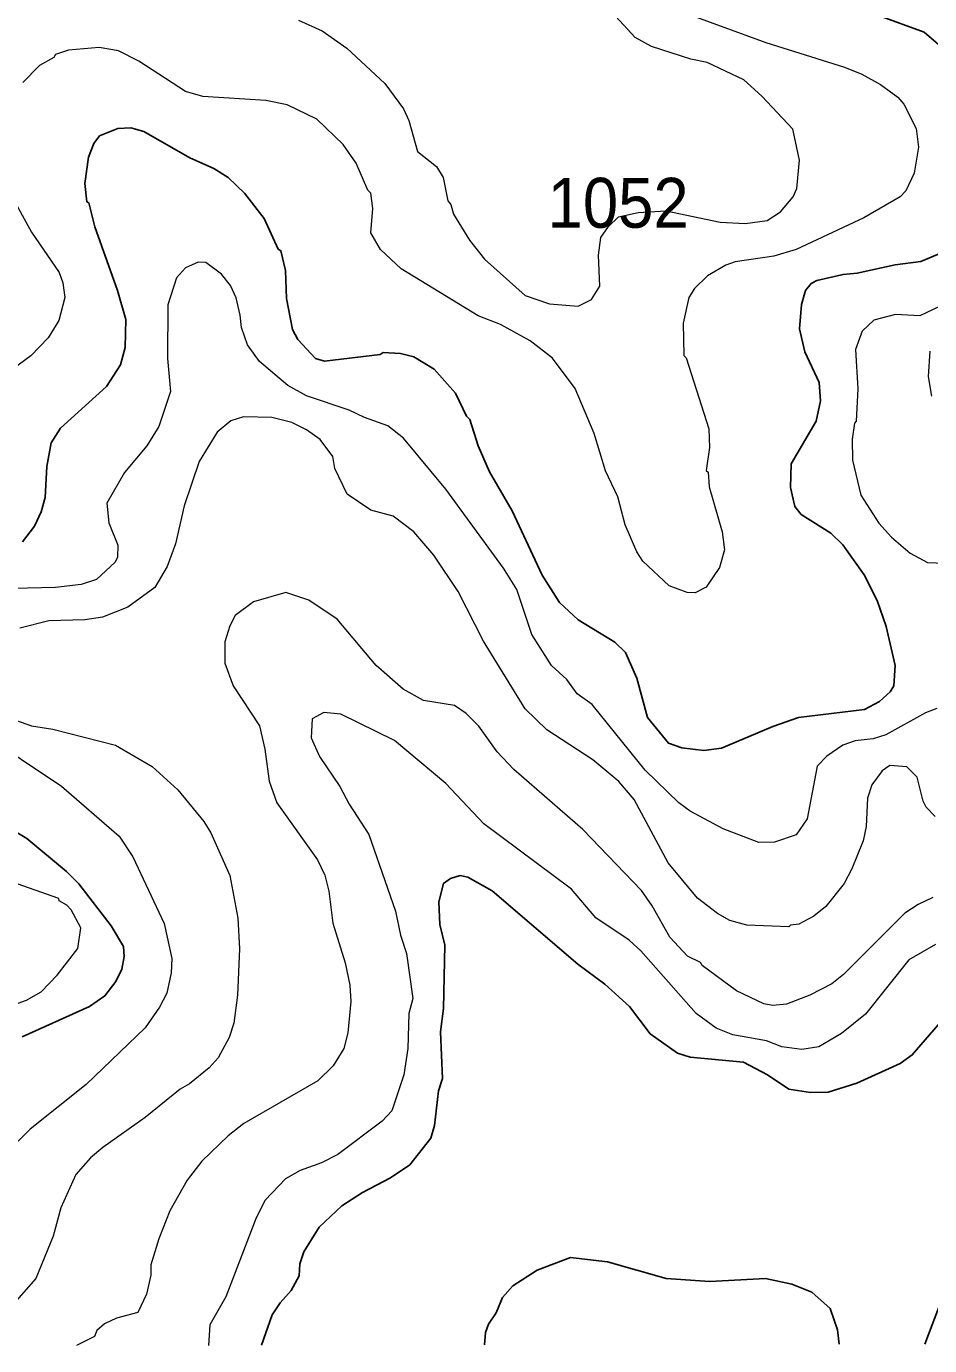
# Model space of a CAD drawing. Extents: x 447.8 to 473.9, y 7733.1 to 7760.8.
# Drawn here: x 468.897 to 470.345, y 7733.13 to 7735.245 of the extents above; entities that cross this region are included whole.
import ezdxf

# ---------------------------------------------------------------- set-up
doc = ezdxf.new("R2010")
doc.units = 0
doc.header["$LTSCALE"] = 0.032
doc.layers.add('1', color=7, linetype='Continuous', lineweight=25)
doc.layers.add('2', color=7, linetype='Continuous', lineweight=13)
doc.layers.add('21', color=7, linetype='Continuous')

msp = doc.modelspace()

# ---------------------------------------------------------------- linework, layer by layer
at = {"layer": '1'}
for points in [[(470.1897, 7735.2897), (470.3362, 7735.2357), (470.3783, 7735.1991)], [(469.0646, 7735.082), (469.0438, 7735.0812), (469.0144, 7735.0693), (469.0051, 7735.0569), (468.9966, 7735.0351), (468.9909, 7734.9928)], [(470.3674, 7734.8834), (470.3308, 7734.868), (470.2894, 7734.8624), (470.2285, 7734.8491), (470.206, 7734.8472), (470.1641, 7734.8374), (470.155, 7734.8328), (470.146, 7734.8215), (470.1395, 7734.7988), (470.1364, 7734.7601), (470.1447, 7734.7232), (470.1675, 7734.674), (470.17, 7734.6447), (470.1628, 7734.6119), (470.1227, 7734.5438), (470.1219, 7734.5054), (470.1285, 7734.4753), (470.139, 7734.4622), (470.1863, 7734.4325), (470.2055, 7734.414), (470.2399, 7734.3659), (470.2604, 7734.3248), (470.275, 7734.2826), (470.2894, 7734.2203), (470.2875, 7734.1877), (470.2816, 7734.178), (470.2644, 7734.1624), (470.2401, 7734.15), (470.1347, 7734.1368), (470.0935, 7734.1224), (470.0112, 7734.0876), (469.9831, 7734.0842), (469.9476, 7734.0882), (469.926, 7734.0957), (469.8927, 7734.1371), (469.8757, 7734.1999), (469.8573, 7734.2412), (469.84, 7734.2578), (469.7816, 7734.2936), (469.7518, 7734.3213), (469.7239, 7734.3654), (469.6756, 7734.4685), (469.6395, 7734.531), (469.6211, 7734.5727), (469.6078, 7734.6149), (469.6023, 7734.6199), (469.5846, 7734.6567), (469.5509, 7734.6951), (469.5183, 7734.7149), (469.4966, 7734.7206), (469.469, 7734.7221), (469.4643, 7734.719), (469.3751, 7734.7079), (469.3604, 7734.7126), (469.3324, 7734.743), (469.3234, 7734.7588), (469.3139, 7734.8084), (469.3122, 7734.8536), (469.3051, 7734.8852), (469.3008, 7734.8878), (469.278, 7734.9366), (469.2467, 7734.9776), (469.2204, 7735.0025), (469.1976, 7735.0171), (469.1589, 7735.034), (469.0854, 7735.0764), (469.0646, 7735.082)], [(468.9909, 7734.9928), (468.9941, 7734.9638), (468.9974, 7734.9619), (469.0066, 7734.9236), (469.0432, 7734.8215), (469.0565, 7734.775), (469.0557, 7734.7301), (469.0482, 7734.7022), (469.0253, 7734.6676), (468.9518, 7734.6006), (468.9369, 7734.577), (468.9298, 7734.5394), (468.927, 7734.4897), (468.9206, 7734.4665), (468.91, 7734.4436), (468.891, 7734.4188)], [(468.7994, 7734.0019), (468.8981, 7733.9428), (468.9615, 7733.8899), (468.981, 7733.8703), (469.0331, 7733.803), (469.0529, 7733.7698), (469.0541, 7733.7538), (469.0502, 7733.7334), (469.0405, 7733.7136), (469.0229, 7733.6906), (468.9981, 7733.674), (468.8904, 7733.6253)], [(470.3651, 7733.6523), (470.3169, 7733.5962), (470.2977, 7733.5825), (470.2282, 7733.5509), (470.182, 7733.5367), (470.1536, 7733.5358), (470.119, 7733.5415), (470.0851, 7733.5643), (470.0466, 7733.5843), (469.9612, 7733.5927), (469.9407, 7733.5988), (469.8968, 7733.6301), (469.8637, 7733.6736), (469.824, 7733.7095), (469.7807, 7733.7416), (469.6436, 7733.8594), (469.6048, 7733.8812), (469.5921, 7733.8837), (469.5769, 7733.8788), (469.5659, 7733.871), (469.5583, 7733.8417), (469.5597, 7733.805), (469.568, 7733.7719), (469.5656, 7733.6703), (469.5608, 7733.633), (469.5639, 7733.5582), (469.5575, 7733.5387), (469.5514, 7733.4828), (469.5454, 7733.4626), (469.5116, 7733.4201), (469.4809, 7733.399), (469.4358, 7733.3755), (469.4026, 7733.3544), (469.3665, 7733.3201), (469.3418, 7733.2806), (469.3355, 7733.2613), (469.3345, 7733.2421), (469.3216, 7733.2183), (469.304, 7733.1988), (469.2913, 7733.1796), (469.2741, 7733.1307)], [(469.6315, 7733.1314), (469.6328, 7733.151), (469.6378, 7733.1646), (469.6501, 7733.183), (469.6603, 7733.2074), (469.6768, 7733.2262), (469.7159, 7733.2514), (469.769, 7733.2713), (469.8285, 7733.2647), (469.9227, 7733.2376), (469.9923, 7733.2329), (470.0817, 7733.2376), (470.124, 7733.2289), (470.1561, 7733.2159), (470.1851, 7733.1895), (470.1972, 7733.1555), (470.1997, 7733.1327), (470.1997, 7733.1324)], [(470.337, 7733.1326), (470.3607, 7733.1944)]]:
    msp.add_lwpolyline(points, dxfattribs=at)
at = {"layer": '2'}
for points in [[(469.3333, 7735.2546), (469.3711, 7735.2374), (469.4106, 7735.2097), (469.4718, 7735.1534), (469.5017, 7735.1127), (469.5102, 7735.0941), (469.524, 7735.0445), (469.5543, 7735.0203), (469.5653, 7735.0027), (469.5727, 7734.9652), (469.5775, 7734.9593), (469.5819, 7734.9436), (469.6075, 7734.9019), (469.6311, 7734.8715), (469.6966, 7734.8136), (469.7356, 7734.8001), (469.7813, 7734.7963), (469.8027, 7734.8072), (469.8164, 7734.8284), (469.8141, 7734.8783), (469.818, 7734.9062), (469.8302, 7734.9241), (469.846, 7734.9395), (469.8778, 7734.9467), (469.9223, 7734.949), (470.0092, 7734.9307), (470.0489, 7734.9289), (470.0845, 7734.9339), (470.1056, 7734.9474), (470.126, 7734.9717), (470.1321, 7734.9847), (470.1363, 7735.0306), (470.1256, 7735.0798), (470.076, 7735.1328), (470.047, 7735.1592), (469.9883, 7735.1869), (469.962, 7735.192), (469.8989, 7735.2125), (469.8726, 7735.2271), (469.8412, 7735.2611)], [(469.9652, 7735.2618), (470.0824, 7735.2191), (470.2084, 7735.1796), (470.2362, 7735.168), (470.266, 7735.1514), (470.2936, 7735.1314), (470.3032, 7735.1203), (470.323, 7735.0812), (470.3271, 7735.0511), (470.3199, 7735.0095)], [(470.0952, 7734.8762), (470.0333, 7734.8673), (470.0181, 7734.8623), (469.989, 7734.8451), (469.9679, 7734.8245), (469.9587, 7734.8101), (469.9496, 7734.769), (469.951, 7734.7175), (469.9548, 7734.7136), (469.9911, 7734.5995), (469.992, 7734.5698), (469.9865, 7734.5328), (469.9896, 7734.5302), (469.9914, 7734.5066), (470.0122, 7734.4345), (470.016, 7734.406), (470.0079, 7734.3772), (469.9865, 7734.3457), (469.9688, 7734.3368), (469.9559, 7734.3375), (469.9272, 7734.3479), (469.8849, 7734.3875), (469.8754, 7734.4025), (469.8568, 7734.4457), (469.8451, 7734.4905), (469.8255, 7734.5326), (469.8071, 7734.592), (469.7764, 7734.6644), (469.7405, 7734.7131), (469.7046, 7734.7405), (469.6572, 7734.7669), (469.6214, 7734.7808), (469.4977, 7734.8559), (469.4648, 7734.887), (469.4493, 7734.9136), (469.4525, 7734.953), (469.4493, 7734.9775), (469.4446, 7734.982), (469.4257, 7735.0258), (469.4051, 7735.0552), (469.3626, 7735.0958), (469.3152, 7735.119), (469.281, 7735.1261), (469.18, 7735.1326), (469.1519, 7735.1403), (469.0771, 7735.1888), (469.045, 7735.2056), (469.0137, 7735.2111), (468.9645, 7735.2069), (468.9436, 7735.1995), (468.941, 7735.1951), (468.9183, 7735.1822), (468.8912, 7735.1547)], [(468.8539, 7735.0072), (468.9054, 7734.9152), (468.9499, 7734.8504), (468.9557, 7734.8336), (468.9589, 7734.8104), (468.949, 7734.7731), (468.932, 7734.7453), (468.9045, 7734.7168), (468.8757, 7734.6959)], [(470.3199, 7735.0095), (470.3066, 7734.981), (470.2976, 7734.9717), (470.2395, 7734.9378), (470.1307, 7734.8869), (470.0952, 7734.8762)], [(469.5694, 7734.5028), (469.5016, 7734.5848), (469.4766, 7734.6043), (469.4388, 7734.6177), (469.4147, 7734.6295), (469.346, 7734.6527), (469.3163, 7734.6689), (469.2709, 7734.7075), (469.2517, 7734.7344), (469.2418, 7734.7619), (469.24, 7734.7821), (469.2331, 7734.8097), (469.2241, 7734.8295), (469.2098, 7734.8478), (469.1845, 7734.8664), (469.1727, 7734.8669), (469.1522, 7734.8578), (469.1376, 7734.8416), (469.1241, 7734.7982), (469.1232, 7734.7122), (469.1279, 7734.6597), (469.1094, 7734.6036), (469.0902, 7734.5724), (469.0545, 7734.5299), (469.0262, 7734.4805), (469.0295, 7734.449), (469.0437, 7734.4134), (469.043, 7734.3942), (469.0395, 7734.3862), (469.0094, 7734.3583), (468.985, 7734.3504), (468.9439, 7734.3455), (468.8536, 7734.3431)], [(470.373, 7734.8019), (470.329, 7734.781), (470.2898, 7734.783), (470.2555, 7734.7741), (470.2365, 7734.7561), (470.2261, 7734.7266), (470.2294, 7734.6639), (470.2269, 7734.6119), (470.2242, 7734.6088), (470.2205, 7734.583), (470.2212, 7734.5494), (470.2347, 7734.4936), (470.2635, 7734.4483), (470.2836, 7734.4258), (470.3137, 7734.4004), (470.3411, 7734.3854), (470.3826, 7734.3838)], [(470.3449, 7734.7242), (470.3424, 7734.6836), (470.3478, 7734.6518)], [(469.7315, 7734.1174), (469.6964, 7734.1511), (469.6296, 7734.2591), (469.589, 7734.3387), (469.5499, 7734.3973), (469.5182, 7734.4346), (469.485, 7734.4598), (469.4492, 7734.4693), (469.4113, 7734.4952), (469.3917, 7734.5363), (469.3882, 7734.5555), (469.3678, 7734.5824), (469.3461, 7734.5983), (469.3226, 7734.6098), (469.2906, 7734.6179), (469.2451, 7734.6187), (469.225, 7734.6123), (469.203, 7734.5944), (469.1743, 7734.5471), (469.15, 7734.4763), (469.1361, 7734.4153), (469.123, 7734.3788), (469.103, 7734.3454), (469.0598, 7734.314), (469.0192, 7734.2977), (468.9906, 7734.2937), (468.9331, 7734.2917), (468.8864, 7734.2803)], [(469.7632, 7734.1981), (469.7385, 7734.2206), (469.7073, 7734.2701), (469.6834, 7734.3421), (469.6616, 7734.3764), (469.5694, 7734.5028)], [(470.35, 7733.8483), (470.3262, 7733.8371), (470.3052, 7733.8232), (470.2067, 7733.7249), (470.1879, 7733.7099), (470.1528, 7733.692), (470.1151, 7733.6777), (470.0935, 7733.6752), (470.079, 7733.6782), (470.035, 7733.6989), (469.9803, 7733.7393), (469.9774, 7733.7443), (469.9565, 7733.7543), (469.9281, 7733.7849), (469.9002, 7733.835), (469.8828, 7733.8599), (469.789, 7733.9576), (469.6785, 7734.0537), (469.6518, 7734.082), (469.622, 7734.1231), (469.6019, 7734.1432), (469.583, 7734.1562), (469.5334, 7734.164), (469.5009, 7734.1825), (469.4576, 7734.2201), (469.3951, 7734.2947), (469.3499, 7734.3253), (469.3128, 7734.3374), (469.2613, 7734.3226), (469.2315, 7734.3005), (469.2231, 7734.2841), (469.2154, 7734.2585), (469.2152, 7734.2242), (469.2283, 7734.188), (469.2707, 7734.1238), (469.2794, 7734.0861), (469.2865, 7734.0351), (469.2986, 7734.0003), (469.3639, 7733.9087), (469.3754, 7733.8844), (469.3819, 7733.8587), (469.3883, 7733.8074), (469.4081, 7733.7438), (469.4156, 7733.708), (469.4173, 7733.6817), (469.4123, 7733.6313), (469.406, 7733.6064), (469.3888, 7733.5786), (469.3643, 7733.5547), (469.2455, 7733.4862), (469.2204, 7733.4662), (469.1782, 7733.4258), (469.155, 7733.3952), (469.127, 7733.3463), (469.1093, 7733.3014)], [(470.3561, 7734.1513), (470.3381, 7734.1445), (470.2745, 7734.1093), (470.2544, 7734.1026), (470.2256, 7734.0994), (470.2058, 7734.0928), (470.1799, 7734.0748), (470.1644, 7734.0591), (470.1483, 7733.9745), (470.1308, 7733.949), (470.0959, 7733.937), (470.0711, 7733.9367), (470.0137, 7733.9584), (469.9609, 7733.9867), (469.943, 7734.0002), (469.8889, 7734.0526), (469.8038, 7734.1576), (469.7799, 7734.1751), (469.7632, 7734.1981)], [(468.8634, 7734.1385), (468.9052, 7734.1235), (468.9395, 7734.1185), (469.0399, 7734.0924), (469.0988, 7734.0584), (469.1397, 7734.021), (469.1814, 7733.9705), (469.193, 7733.952), (469.2233, 7733.8837), (469.2361, 7733.8151), (469.2386, 7733.7661), (469.2354, 7733.6917), (469.2298, 7733.6468), (469.2219, 7733.6243), (469.2044, 7733.5917), (469.1902, 7733.5756), (469.1586, 7733.5496), (469.1434, 7733.5411), (469.0875, 7733.4961), (469.0194, 7733.448), (469.0001, 7733.4313), (468.9766, 7733.4045), (468.9521, 7733.3508), (468.9401, 7733.3059), (468.9123, 7733.2377), (468.8775, 7733.198)], [(470.3542, 7733.7733), (470.3115, 7733.7487), (470.2422, 7733.6617), (470.2034, 7733.6305), (470.1674, 7733.6089), (470.14, 7733.6048), (470.1078, 7733.6093), (470.0831, 7733.6186), (470.0296, 7733.6285), (470.0028, 7733.6393), (469.9706, 7733.6625), (469.8817, 7733.7631), (469.8632, 7733.7801), (469.81, 7733.8157), (469.771, 7733.8618), (469.6303, 7733.9665), (469.5695, 7734.0312), (469.4872, 7734.0999), (469.4009, 7734.1426), (469.3736, 7734.145), (469.3551, 7734.1347), (469.3534, 7734.1043), (469.3669, 7734.0745), (469.3996, 7734.0263), (469.4145, 7733.9981), (469.4461, 7733.9494), (469.4887, 7733.8267), (469.4968, 7733.7882), (469.5064, 7733.7588), (469.5166, 7733.6865), (469.5103, 7733.6628), (469.5087, 7733.6067), (469.5021, 7733.5643), (469.4827, 7733.5066), (469.4676, 7733.4899), (469.3965, 7733.4363)], [(468.8221, 7734.1143), (468.9534, 7734.0269), (469.0456, 7733.9467), (469.068, 7733.9139), (469.1182, 7733.807), (469.1303, 7733.7506), (469.1294, 7733.7275), (469.1223, 7733.695), (469.1106, 7733.6726), (469.0875, 7733.6398), (468.993, 7733.5486), (468.9032, 7733.4771), (468.8648, 7733.4394)], [(469.9725, 7733.8472), (469.9257, 7733.9041), (469.871, 7734.0054), (469.8466, 7734.0345), (469.805, 7734.069), (469.7315, 7734.1174)], [(470.3534, 7733.9785), (470.3391, 7733.9933), (470.3342, 7734.0027), (470.3246, 7734.0414), (470.3081, 7734.0578), (470.2812, 7734.0598), (470.2688, 7734.0514), (470.2522, 7734.029), (470.2454, 7734.0075), (470.2429, 7733.9623), (470.238, 7733.9395), (470.2203, 7733.8946), (470.2078, 7733.8711), (470.1786, 7733.8338), (470.1589, 7733.8184), (470.1351, 7733.8058), (470.1215, 7733.8043), (470.1191, 7733.8012), (470.0517, 7733.8044), (470.0246, 7733.8117), (470.0048, 7733.8228), (469.9725, 7733.8472)], [(468.8484, 7733.6663), (468.8975, 7733.684), (468.9209, 7733.6974), (468.9467, 7733.724), (468.9794, 7733.7666), (468.9844, 7733.8), (468.9689, 7733.8286), (468.962, 7733.8363), (468.9496, 7733.8433), (468.949, 7733.8467), (468.8438, 7733.8835)], [(469.3965, 7733.4363), (469.3703, 7733.4232), (469.3358, 7733.4109), (469.3125, 7733.3973), (469.2799, 7733.3632), (469.2654, 7733.3349)], [(469.2654, 7733.3349), (469.2168, 7733.2085), (469.1912, 7733.1635), (469.1888, 7733.1306)], [(469.1093, 7733.3014), (469.0967, 7733.2597), (469.0965, 7733.2433), (469.0894, 7733.2127), (469.0757, 7733.1833), (469.0414, 7733.1743)], [(469.0414, 7733.1743), (469.0221, 7733.1652), (469.0101, 7733.1546), (469.0062, 7733.1449), (468.9901, 7733.1367), (468.9773, 7733.1302)]]:
    msp.add_lwpolyline(points, dxfattribs=at)

# ---------------------------------------------------------------- texts
at = {"layer": '21', "width": 0.95}
msp.add_text('1052', height=0.08, dxfattribs=at).set_placement((469.7325, 7734.922))

doc.saveas('drawing.dxf')
